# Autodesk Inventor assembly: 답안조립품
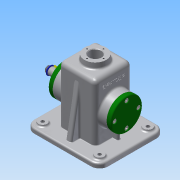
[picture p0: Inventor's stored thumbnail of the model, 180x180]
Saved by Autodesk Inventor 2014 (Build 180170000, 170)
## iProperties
Created: 2015-12
Part Number: 답안조립품
Document SubType Name: Assembly
Designer: Administrator
Author: Administrator
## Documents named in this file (13)
- D:\451225V1013\답안조립품.iam
- D:\451225V1013\본체.ipt
- D:\451225V1013\편심축.ipt
- D:\451225V1013\볼트 M6 x 12.ipt
- D:\451225V1013\와셔.ipt
- D:\451225V1013\키 5 x 5 x 14.ipt
- D:\451225V1013\V-벨트풀리.ipt
- D:\451225V1013\멈춤링 15 x 1.ipt
- D:\451225V1013\베어링 15 x 35 x 11.ipt
- D:\451225V1013\앞커버.ipt
- D:\451225V1013\오일실 15 25 7.ipt
- D:\451225V1013\볼트 M4 x 10.ipt
- D:\451225V1013\뒤커버.ipt
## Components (10 placed, 3 different names)
1. ISO 4018 M6 x 12:1
2. V-벨트풀리:1
3. ISO 4762 M4 x 10:1
4. ISO 4762 M4 x 10:2
5. ISO 4762 M4 x 10:3
6. ISO 4762 M4 x 10:4
7. ISO 4762 M4 x 10:5
8. ISO 4762 M4 x 10:6
9. ISO 4762 M4 x 10:7
10. ISO 4762 M4 x 10:8
